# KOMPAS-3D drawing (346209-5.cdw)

Referenced files: С1-2.cdw
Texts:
  КП.ОКМЧЕП.МЕ.12-01.000СП
  Текст на чертеже
  Размерные надписи
  Шероховатость
  Линия-выноска #1
  Линия-выноска #2
  Линия-выноска #3
  Отклонения формы и база
  Заголовок таблицы
  Ячейка таблицы
  Стрелка вида
  Обозначение изменения
  Фигурная скобка
  Номер узла
  Марка координационной оси
  VRCB
  Выносная надпись
  Обозначение узла
  Марка/позиционное обозначение с линией-выноской
  Марка/позиционное обозначение на линии
  Марка/позиционное обозначение без линии-выноски
  Пробка до маслозливного отвору
  Болти ГОСТ 7798-70
  Гайки ГОСТ 5915-70
  Шайби ГОСТ 6402-70
  КП.ОКМЧЕП.МЕ.11.01.000СП-
  КП.ОКМЧЕП.МЕ.12-01.019
  КП.ОКМЧЕП.МЕ.12-01.020
  Кришка оглядового отвору
  Підшипники ТУ37.006.162-89
  КП.ОКМЧЕП.МЕ.12-01.021
  КП.ОКМЧЕП.МЕ.12-01.022
  Віддушина з ковпачком та сіткою
  Стандартні вироби
  Манжети ГОСТ 8752-79
Dimensions and other numbers on the sheet: 7; 1:1; 1; 19; 20; 25; 26; 24; 4; 27; 30; 8,65Г; 6; 21; 29; 32; 309; 12,65Г; 22; 28; 34; 40; 306; 10,65Г; 2; 23; 33; 31; 0; 3; 5; 8; 9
